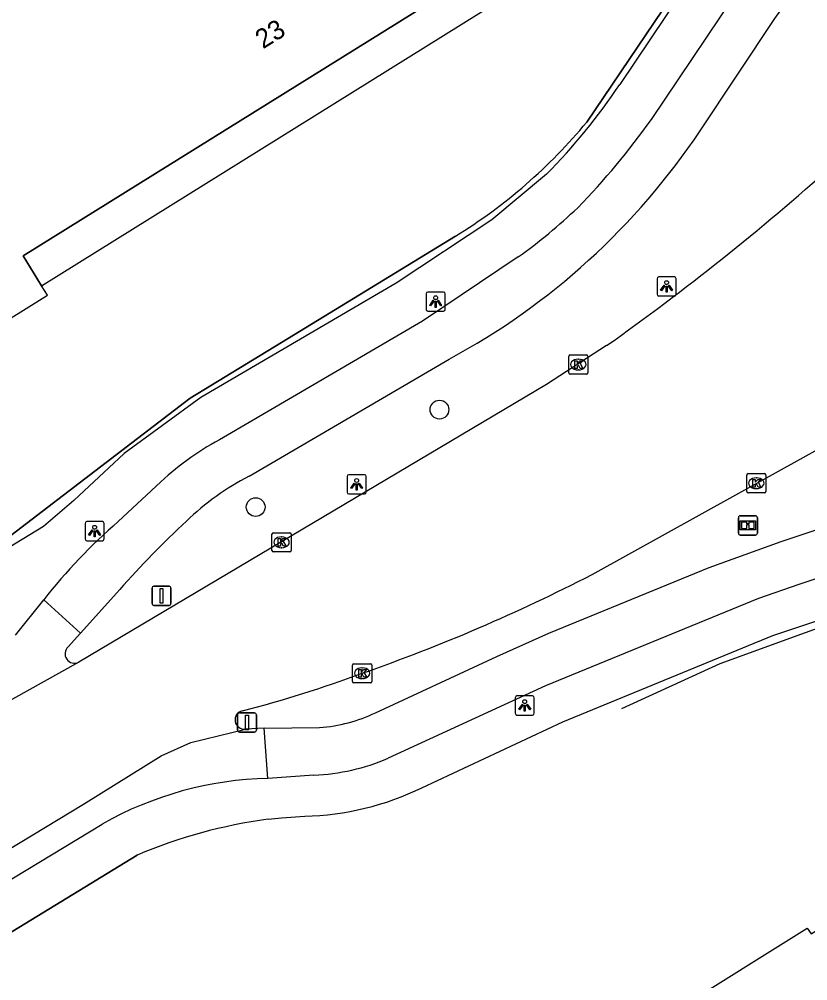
# Model space of a CAD drawing. Extents: x 156651 to 158072, y 387631 to 388990.
# Drawn here: x 157913 to 157954.1, y 388531.2 to 388581.4 of the extents above; entities that cross this region are included whole.
import ezdxf

# ---------------------------------------------------------------- set-up
doc = ezdxf.new("R2010")
doc.units = 0
for name, color, linetype in [('IMGEO_Boom', 7, 'Continuous'), ('IMGEO_Fietspad_open', 7, 'Continuous'), ('IMGEO_Groenvoorziening', 7, 'Continuous'), ('IMGEO_Hek', 7, 'Continuous'), ('IMGEO_Informatiebord', 7, 'Continuous'), ('IMGEO_Kolk', 7, 'Continuous'), ('IMGEO_Lichtpunt', 7, 'Continuous'), ('IMGEO_Muur', 7, 'Continuous'), ('IMGEO_Pand', 7, 'Continuous'), ('IMGEO_Pand_nummerreeks', 7, 'Continuous'), ('IMGEO_Pand_overbouw', 7, 'Continuous'), ('IMGEO_Rijbaan_lokaal_gesloten', 7, 'Continuous'), ('IMGEO_Verkeersbordpaal', 7, 'Continuous'), ('IMGEO_Voetpad_open', 7, 'Continuous')]:
    doc.layers.add(name, color=color, linetype=linetype)

msp = doc.modelspace()

# ---------------------------------------------------------------- linework, layer by layer
at = {"layer": 'IMGEO_Boom'}
for centre in [(157934.929, 388561.003), (157925.351, 388555.924)]:
    msp.add_circle(centre, 0.489, dxfattribs=at)
at = {"layer": 'IMGEO_Fietspad_open'}
for points in [[(157953.825, 388587.483), (157950.99, 388583.61), (157945.972, 388576.134)], [(157948.511, 388575.538), (157952.413, 388581.397), (157954.927, 388584.899)], [(157939.034, 388568.961), (157934.042, 388565.621), (157923.682, 388559.554)], [(157925.008, 388557.539), (157935.436, 388563.635)], [(157931.599, 388545.204), (157937.919, 388548.129), (157940.636, 388549.355), (157948.985, 388552.768), (157952.731, 388554.135), (157964.136, 388557.918), (157970.227, 388560.472)], [(157975.692, 388560.117), (157964.836, 388555.593), (157953.656, 388551.883), (157951.558, 388551.166), (157940.45, 388546.612), (157932.252, 388542.83)], [(157920.413, 388557.247), (157918.184, 388555.166)], [(157916.219, 388549.358), (157918.263, 388551.623)], [(157925.789, 388544.405), (157928.683, 388544.428)], [(157928.387, 388541.952), (157925.989, 388541.781)]]:
    msp.add_lwpolyline(points, dxfattribs=at)
for centre, radius, start, end in [((157915.537, 388597.592), 37.239, 315.5843, 324.8144), ((157918.015, 388595.904), 36.671, 298.3632, 326.264), ((157921.547, 388593.233), 29.915, 305.7707, 313.4907), ((157930.888, 388545.874), 15.461, 117.7771, 132.6457), ((157931.627, 388544.891), 14.275, 117.6236, 133.813), ((157937.074, 388533.312), 28.887, 130.8394, 142.0133), ((157957.425, 388516.909), 52.333, 132.985, 138.4453), ((157928.064, 388552.621), 8.216, 274.3205, 295.4837), ((157927.957, 388552.792), 10.848, 272.2725, 293.3245)]:
    msp.add_arc(centre, radius, start, end, dxfattribs=at)
at = {"layer": 'IMGEO_Groenvoorziening'}
for points in [[(157942.609, 388575.997), (157948.757, 388585.103), (157945.61, 388590.115), (157919.697, 388631.383), (157907.31, 388623.673)], [(157876.307, 388544.438), (157879.966, 388539.6), (157881.966, 388538.145), (157884.382, 388537.75), (157886.516, 388538.265), (157912.593, 388554.443), (157921.94, 388561.605), (157926.695, 388564.507), (157935.759, 388570.044)]]:
    msp.add_lwpolyline(points, dxfattribs=at)
msp.add_arc((157921.347, 388593.545), 27.568, 301.5184, 320.4662, dxfattribs=at)
at = {"layer": 'IMGEO_Hek'}
for points in [[(157945.61, 388590.115), (157948.757, 388585.103), (157942.609, 388575.997)], [(157935.759, 388570.044), (157926.695, 388564.507)], [(157926.695, 388564.507), (157921.94, 388561.605), (157912.593, 388554.443), (157886.516, 388538.265), (157884.382, 388537.75), (157881.966, 388538.145), (157879.966, 388539.6), (157876.307, 388544.438)], [(157919.17, 388537.784), (157901.376, 388526.898)]]:
    msp.add_lwpolyline(points, dxfattribs=at)
for centre, radius, start, end in [((157921.347, 388593.545), 27.568, 301.5184, 320.4662), ((157929.517, 388513.336), 26.547, 97.6193, 112.9393)]:
    msp.add_arc(centre, radius, start, end, dxfattribs=at)
at = {"layer": 'IMGEO_Informatiebord'}
for p, q in [((157950.508, 388554.568), (157950.508, 388555.368)), ((157950.508, 388555.368), (157950.508, 388554.568)), ((157950.608, 388555.468), (157951.398, 388555.468)), ((157951.398, 388555.468), (157950.608, 388555.468)), ((157951.498, 388555.368), (157951.498, 388554.568)), ((157951.498, 388554.568), (157951.498, 388555.368)), ((157951.398, 388554.468), (157950.608, 388554.468)), ((157950.608, 388554.468), (157951.398, 388554.468))]:
    msp.add_line(p, q, dxfattribs=at)
for points in [[(157950.609, 388555.2), (157951.397, 388555.2), (157951.397, 388554.736), (157950.609, 388554.736), (157950.609, 388555.2)], [(157950.674, 388555.135), (157950.674, 388554.801), (157950.949, 388554.801), (157950.95, 388555.014), (157951.054, 388555.015), (157951.055, 388554.801), (157951.332, 388554.801), (157951.332, 388555.135), (157951.056, 388555.135), (157951.056, 388555.055), (157950.95, 388555.055), (157950.95, 388555.135), (157950.674, 388555.135)]]:
    msp.add_lwpolyline(points, dxfattribs=at)
for centre, start, end in [((157950.608, 388555.368), 90, 180), ((157950.608, 388555.368), 90, 180), ((157951.398, 388555.368), 0, 90), ((157951.398, 388555.368), 360, 90), ((157950.608, 388554.568), 180, 270), ((157950.608, 388554.568), 180, 270), ((157951.398, 388554.568), 270, 0), ((157951.398, 388554.568), 270, 0)]:
    msp.add_arc(centre, 0.1, start, end, dxfattribs=at)
at = {"layer": 'IMGEO_Kolk'}
for p, q in [((157941.665, 388562.927), (157941.665, 388563.779)), ((157941.74, 388563.853), (157942.592, 388563.853)), ((157942.153, 388563.633), (157942.178, 388563.633)), ((157942.666, 388563.779), (157942.666, 388562.927)), ((157942.176, 388563.073), (157942.151, 388563.073)), ((157942.592, 388562.853), (157941.74, 388562.853)), ((157950.942, 388556.743), (157950.942, 388557.595)), ((157951.017, 388557.669), (157951.869, 388557.669)), ((157951.943, 388557.595), (157951.943, 388556.743)), ((157951.43, 388557.449), (157951.455, 388557.449)), ((157951.869, 388556.669), (157951.017, 388556.669)), ((157951.453, 388556.889), (157951.428, 388556.889)), ((157926.275, 388554.587), (157927.127, 388554.587)), ((157926.2, 388553.661), (157926.2, 388554.513)), ((157926.688, 388554.367), (157926.713, 388554.367)), ((157927.201, 388554.513), (157927.201, 388553.661)), ((157927.127, 388553.587), (157926.275, 388553.587)), ((157926.711, 388553.807), (157926.686, 388553.807)), ((157930.4, 388546.834), (157930.4, 388547.686)), ((157930.475, 388547.76), (157931.327, 388547.76)), ((157930.888, 388547.54), (157930.913, 388547.54)), ((157931.401, 388547.686), (157931.401, 388546.834)), ((157931.327, 388546.76), (157930.475, 388546.76)), ((157930.911, 388546.98), (157930.886, 388546.98))]:
    msp.add_line(p, q, dxfattribs=at)
for points in [[(157941.665, 388562.927), (157941.665, 388563.779)], [(157941.74, 388563.853), (157942.592, 388563.853)], [(157941.986, 388563.553), (157942.109, 388563.553), (157942.109, 388563.402), (157942.239, 388563.553), (157942.403, 388563.553), (157942.257, 388563.402), (157942.41, 388563.153), (157942.258, 388563.153), (157942.173, 388563.317), (157942.109, 388563.25), (157942.109, 388563.153), (157941.986, 388563.153), (157941.986, 388563.553)], [(157942.666, 388563.779), (157942.666, 388562.927)], [(157942.592, 388562.853), (157941.74, 388562.853)], [(157950.942, 388556.743), (157950.942, 388557.595)], [(157951.017, 388557.669), (157951.869, 388557.669)], [(157951.943, 388557.595), (157951.943, 388556.743)], [(157951.263, 388557.369), (157951.386, 388557.369), (157951.386, 388557.218), (157951.516, 388557.369), (157951.68, 388557.369), (157951.534, 388557.218), (157951.687, 388556.969), (157951.535, 388556.969), (157951.45, 388557.133), (157951.386, 388557.066), (157951.386, 388556.969), (157951.263, 388556.969), (157951.263, 388557.369)], [(157951.869, 388556.669), (157951.017, 388556.669)], [(157926.275, 388554.587), (157927.127, 388554.587)], [(157926.2, 388553.661), (157926.2, 388554.513)], [(157926.521, 388554.287), (157926.644, 388554.287), (157926.644, 388554.136), (157926.774, 388554.287), (157926.938, 388554.287), (157926.792, 388554.136), (157926.945, 388553.887), (157926.793, 388553.887), (157926.708, 388554.051), (157926.644, 388553.984), (157926.644, 388553.887), (157926.521, 388553.887), (157926.521, 388554.287)], [(157927.201, 388554.513), (157927.201, 388553.661)], [(157927.127, 388553.587), (157926.275, 388553.587)], [(157930.4, 388546.834), (157930.4, 388547.686)], [(157930.475, 388547.76), (157931.327, 388547.76)], [(157931.401, 388547.686), (157931.401, 388546.834)], [(157930.721, 388547.46), (157930.844, 388547.46), (157930.844, 388547.309), (157930.974, 388547.46), (157931.138, 388547.46), (157930.992, 388547.309), (157931.145, 388547.06), (157930.993, 388547.06), (157930.908, 388547.224), (157930.844, 388547.157), (157930.844, 388547.06), (157930.721, 388547.06), (157930.721, 388547.46)], [(157931.327, 388546.76), (157930.475, 388546.76)]]:
    msp.add_lwpolyline(points, dxfattribs=at)
for centre, start, end in [((157941.742, 388563.777), 91.552, 178.448), ((157941.742, 388563.777), 91.552, 178.448), ((157942.59, 388563.777), 1.552, 88.448), ((157942.59, 388563.777), 1.552, 88.448), ((157941.742, 388562.929), 181.552, 268.448), ((157941.742, 388562.929), 181.552, 268.448), ((157942.59, 388562.929), 271.552, 358.448), ((157942.59, 388562.929), 271.552, 358.448), ((157951.019, 388557.593), 91.552, 178.448), ((157951.019, 388557.593), 91.552, 178.448), ((157951.867, 388557.593), 1.552, 88.448), ((157951.867, 388557.593), 1.552, 88.448), ((157951.019, 388556.745), 181.552, 268.448), ((157951.019, 388556.745), 181.552, 268.448), ((157951.867, 388556.745), 271.552, 358.448), ((157951.867, 388556.745), 271.552, 358.448), ((157926.277, 388554.511), 91.552, 178.448), ((157926.277, 388554.511), 91.552, 178.448), ((157927.125, 388554.511), 1.552, 88.448), ((157927.125, 388554.511), 1.552, 88.448), ((157926.277, 388553.663), 181.552, 268.448), ((157926.277, 388553.663), 181.552, 268.448), ((157927.125, 388553.663), 271.552, 358.448), ((157927.125, 388553.663), 271.552, 358.448), ((157930.477, 388547.684), 91.552, 178.448), ((157930.477, 388547.684), 91.552, 178.448), ((157931.325, 388547.684), 1.552, 88.448), ((157931.325, 388547.684), 1.552, 88.448), ((157930.477, 388546.836), 181.552, 268.448), ((157930.477, 388546.836), 181.552, 268.448), ((157931.325, 388546.836), 271.552, 358.448), ((157931.325, 388546.836), 271.552, 358.448)]:
    msp.add_arc(centre, 0.0765, start, end, dxfattribs=at)
for centre, major_axis, ratio, start_param, end_param in [((157942.152, 388563.353), (-0.387, 0.002), 0.722429, 4.712389, 7.853982), ((157942.177, 388563.353), (-0.39, 0.002), 0.717154, 1.570796, 4.712389), ((157951.429, 388557.169), (-0.387, 0.002), 0.722429, 4.712389, 7.853982), ((157951.454, 388557.169), (-0.39, 0.002), 0.717154, 1.570796, 4.712389), ((157926.687, 388554.087), (-0.387, 0.002), 0.722429, 4.712389, 7.853982), ((157926.712, 388554.087), (-0.39, 0.002), 0.717154, 1.570796, 4.712389), ((157930.887, 388547.26), (-0.387, 0.002), 0.722429, 4.712389, 7.853982), ((157930.912, 388547.26), (-0.39, 0.002), 0.717154, 1.570796, 4.712389)]:
    msp.add_ellipse(centre, major_axis=major_axis, ratio=ratio, start_param=start_param, end_param=end_param, dxfattribs=at)
at = {"layer": 'IMGEO_Lichtpunt'}
for p, q in [((157946.27, 388567.828), (157946.27, 388567.021)), ((157946.27, 388567.828), (157946.27, 388567.021)), ((157947.172, 388567.923), (157946.364, 388567.923)), ((157947.172, 388567.923), (157946.364, 388567.923)), ((157947.266, 388567.021), (157947.266, 388567.828)), ((157947.266, 388567.021), (157947.266, 388567.828)), ((157935.135, 388567.133), (157934.327, 388567.133)), ((157935.135, 388567.133), (157934.327, 388567.133)), ((157934.233, 388567.038), (157934.233, 388566.231)), ((157934.233, 388567.038), (157934.233, 388566.231)), ((157935.229, 388566.231), (157935.229, 388567.038)), ((157935.229, 388566.231), (157935.229, 388567.038)), ((157946.364, 388566.927), (157947.172, 388566.927)), ((157946.364, 388566.927), (157947.172, 388566.927)), ((157934.327, 388566.137), (157935.135, 388566.137)), ((157934.327, 388566.137), (157935.135, 388566.137)), ((157931.017, 388557.608), (157930.209, 388557.608)), ((157931.017, 388557.608), (157930.209, 388557.608)), ((157930.115, 388557.513), (157930.115, 388556.706)), ((157930.115, 388557.513), (157930.115, 388556.706)), ((157931.111, 388556.706), (157931.111, 388557.513)), ((157931.111, 388556.706), (157931.111, 388557.513)), ((157930.209, 388556.612), (157931.017, 388556.612)), ((157930.209, 388556.612), (157931.017, 388556.612)), ((157916.458, 388555.073), (157916.458, 388554.266)), ((157916.458, 388555.073), (157916.458, 388554.266)), ((157917.36, 388555.168), (157916.552, 388555.168)), ((157917.36, 388555.168), (157916.552, 388555.168)), ((157917.454, 388554.266), (157917.454, 388555.073)), ((157917.454, 388554.266), (157917.454, 388555.073)), ((157916.552, 388554.172), (157917.36, 388554.172)), ((157916.552, 388554.172), (157917.36, 388554.172)), ((157939.777, 388546.081), (157938.969, 388546.081)), ((157939.777, 388546.081), (157938.969, 388546.081)), ((157938.875, 388545.986), (157938.875, 388545.179)), ((157938.875, 388545.986), (157938.875, 388545.179)), ((157939.871, 388545.179), (157939.871, 388545.986)), ((157939.871, 388545.179), (157939.871, 388545.986)), ((157938.969, 388545.085), (157939.777, 388545.085)), ((157938.969, 388545.085), (157939.777, 388545.085))]:
    msp.add_line(p, q, dxfattribs=at)
for points in [[(157946.644, 388567.492), (157946.683, 388567.464), (157946.495, 388567.202), (157946.457, 388567.229), (157946.644, 388567.492)], [(157946.746, 388567.444), (157946.793, 388567.444), (157946.793, 388567.122), (157946.746, 388567.122), (157946.746, 388567.444)], [(157946.856, 388567.464), (157946.894, 388567.491), (157947.081, 388567.229), (157947.042, 388567.201), (157946.856, 388567.464)], [(157934.607, 388566.702), (157934.646, 388566.674), (157934.458, 388566.412), (157934.42, 388566.439), (157934.607, 388566.702)], [(157934.709, 388566.654), (157934.756, 388566.654), (157934.756, 388566.332), (157934.709, 388566.332), (157934.709, 388566.654)], [(157934.819, 388566.674), (157934.857, 388566.701), (157935.044, 388566.439), (157935.005, 388566.411), (157934.819, 388566.674)], [(157930.489, 388557.177), (157930.528, 388557.149), (157930.34, 388556.887), (157930.302, 388556.914), (157930.489, 388557.177)], [(157930.591, 388557.129), (157930.638, 388557.129), (157930.638, 388556.807), (157930.591, 388556.807), (157930.591, 388557.129)], [(157930.701, 388557.149), (157930.739, 388557.176), (157930.926, 388556.914), (157930.887, 388556.886), (157930.701, 388557.149)], [(157916.832, 388554.737), (157916.871, 388554.709), (157916.683, 388554.447), (157916.645, 388554.474), (157916.832, 388554.737)], [(157916.934, 388554.689), (157916.981, 388554.689), (157916.981, 388554.367), (157916.934, 388554.367), (157916.934, 388554.689)], [(157917.044, 388554.709), (157917.082, 388554.736), (157917.269, 388554.474), (157917.23, 388554.446), (157917.044, 388554.709)], [(157939.249, 388545.65), (157939.288, 388545.622), (157939.1, 388545.36), (157939.062, 388545.387), (157939.249, 388545.65)], [(157939.351, 388545.602), (157939.398, 388545.602), (157939.398, 388545.28), (157939.351, 388545.28), (157939.351, 388545.602)], [(157939.461, 388545.622), (157939.499, 388545.649), (157939.686, 388545.387), (157939.647, 388545.359), (157939.461, 388545.622)]]:
    msp.add_lwpolyline(points, dxfattribs=at)
for centre in [(157946.769, 388567.626), (157934.732, 388566.836), (157930.614, 388557.311), (157916.957, 388554.871), (157939.374, 388545.784)]:
    msp.add_circle(centre, 0.0994, dxfattribs=at)
for centre, start, end in [((157946.364, 388567.828), 90, 180), ((157946.364, 388567.828), 90, 180), ((157947.172, 388567.828), 0, 90), ((157947.172, 388567.828), 0, 90), ((157934.327, 388567.038), 90, 180), ((157934.327, 388567.038), 90, 180), ((157935.135, 388567.038), 0, 90), ((157935.135, 388567.038), 0, 90), ((157946.364, 388567.021), 180, 270), ((157946.364, 388567.021), 180, 270), ((157947.172, 388567.021), 270, 0), ((157947.172, 388567.021), 270, 360), ((157934.327, 388566.231), 180, 270), ((157934.327, 388566.231), 180, 270), ((157935.135, 388566.231), 270, 0), ((157935.135, 388566.231), 270, 360), ((157930.209, 388557.513), 90, 180), ((157930.209, 388557.513), 90, 180), ((157931.017, 388557.513), 0, 90), ((157931.017, 388557.513), 0, 90), ((157930.209, 388556.706), 180, 270), ((157930.209, 388556.706), 180, 270), ((157931.017, 388556.706), 270, 0), ((157931.017, 388556.706), 270, 360), ((157916.552, 388555.073), 90, 180), ((157916.552, 388555.073), 90, 180), ((157917.36, 388555.073), 0, 90), ((157917.36, 388555.073), 0, 90), ((157916.552, 388554.266), 180, 270), ((157916.552, 388554.266), 180, 270), ((157917.36, 388554.266), 270, 0), ((157917.36, 388554.266), 270, 360), ((157938.969, 388545.986), 90, 180), ((157938.969, 388545.986), 90, 180), ((157939.777, 388545.986), 0, 90), ((157939.777, 388545.986), 0, 90), ((157938.969, 388545.179), 180, 270), ((157938.969, 388545.179), 180, 270), ((157939.777, 388545.179), 270, 0), ((157939.777, 388545.179), 270, 360)]:
    msp.add_arc(centre, 0.0946, start, end, dxfattribs=at)
at = {"layer": 'IMGEO_Muur'}
msp.add_lwpolyline([(157944.436, 388545.424), (157949.561, 388547.765), (157976.054, 388557.403), (157979.433, 388551.896)], dxfattribs=at)
at = {"layer": 'IMGEO_Pand'}
for points in [[(157914.19, 388567.452), (157913.225, 388569.027), (157942.615, 388587.321), (157933.319, 388602.195), (157924.551, 388596.738), (157917.093, 388592.095), (157902.499, 388615.468), (157898.345, 388612.873), (157889.39, 388607.278), (157889.176, 388607.593), (157883.007, 388603.739), (157883.193, 388603.423), (157865.87, 388592.617), (157891.158, 388552.943), (157908.075, 388563.555), (157908.34, 388563.13), (157914.494, 388566.97), (157914.19, 388567.452)], [(157954.097, 388533.97), (157954.301, 388533.683), (157958.588, 388536.358), (157966.066, 388541.038), (157973.749, 388528.738), (157974.94, 388529.477), (157993.887, 388499.128), (157980.909, 388491.057), (157981.094, 388490.76), (157946.508, 388469.137), (157919.498, 388512.339), (157954.097, 388533.97)]]:
    msp.add_lwpolyline(points, dxfattribs=at)
at = {"layer": 'IMGEO_Pand_overbouw'}
msp.add_lwpolyline([(157943.658, 388585.673), (157943.147, 388586.459), (157942.615, 388587.321), (157913.225, 388569.027), (157914.19, 388567.452), (157942.786, 388585.292), (157942.858, 388585.18)], close=True, dxfattribs=at)
at = {"layer": 'IMGEO_Rijbaan_lokaal_gesloten'}
for points in [[(157942.886, 388552.412), (157967.098, 388565.84)], [(157943.644, 388564.341), (157940.508, 388562.306), (157916.133, 388547.836)], [(157912.832, 388549.247), (157914.307, 388551.091)], [(157914.307, 388551.091), (157916.219, 388549.358)], [(157916.219, 388549.358), (157915.575, 388548.644)], [(157916.133, 388547.836), (157910.853, 388544.897), (157894.34, 388534.897)], [(157801.977, 388465.115), (157808.05, 388470.514), (157814.126, 388475.59), (157822.012, 388481.702), (157827.136, 388485.429), (157832.229, 388488.942), (157838.65, 388493.098), (157881.592, 388519.374), (157884.271, 388521.013), (157916.373, 388540.433), (157920.425, 388542.954), (157921.978, 388543.651), (157924.816, 388544.354)], [(157925.789, 388544.405), (157924.816, 388544.354)], [(157925.989, 388541.781), (157925.789, 388544.405)], [(157900.08, 388528.956), (157917.35, 388539.403)]]:
    msp.add_lwpolyline(points, dxfattribs=at)
for centre, radius, start, end in [((157866.867, 388672.709), 132.809, 305.31667, 311.81023), ((157900.199, 388635.198), 93.143, 289.2458, 297.27711), ((157915.911, 388548.279), 0.496, 132.6143, 296.6432), ((157908.86, 388606.7), 63.395, 284.4304, 290.34557), ((157924.758, 388544.833), 0.482, 101.9591, 276.9069), ((157926.423, 388523.323), 18.463, 91.3472, 119.4333)]:
    msp.add_arc(centre, radius, start, end, dxfattribs=at)
at = {"layer": 'IMGEO_Verkeersbordpaal'}
for p, q in [((157919.948, 388550.898), (157919.948, 388551.698)), ((157919.948, 388551.698), (157919.948, 388550.898)), ((157920.048, 388551.798), (157920.838, 388551.798)), ((157920.838, 388551.798), (157920.048, 388551.798)), ((157920.938, 388551.698), (157920.938, 388550.898)), ((157920.938, 388550.898), (157920.938, 388551.698)), ((157920.838, 388550.798), (157920.048, 388550.798)), ((157920.048, 388550.798), (157920.838, 388550.798)), ((157924.402, 388544.295), (157924.402, 388545.095)), ((157924.402, 388545.095), (157924.402, 388544.295)), ((157924.502, 388545.195), (157925.292, 388545.195)), ((157925.292, 388545.195), (157924.502, 388545.195)), ((157925.392, 388545.095), (157925.392, 388544.295)), ((157925.392, 388544.295), (157925.392, 388545.095)), ((157925.292, 388544.195), (157924.502, 388544.195)), ((157924.502, 388544.195), (157925.292, 388544.195))]:
    msp.add_line(p, q, dxfattribs=at)
for points in [[(157920.368, 388551.673), (157920.518, 388551.673), (157920.518, 388550.923), (157920.368, 388550.923), (157920.368, 388551.673)], [(157924.822, 388545.07), (157924.972, 388545.07), (157924.972, 388544.32), (157924.822, 388544.32), (157924.822, 388545.07)]]:
    msp.add_lwpolyline(points, dxfattribs=at)
for centre, start, end in [((157920.048, 388551.698), 90, 180), ((157920.048, 388551.698), 90, 180), ((157920.838, 388551.698), 0, 90), ((157920.838, 388551.698), 360, 90), ((157920.048, 388550.898), 180, 270), ((157920.048, 388550.898), 180, 270), ((157920.838, 388550.898), 270, 0), ((157920.838, 388550.898), 270, 0), ((157924.502, 388545.095), 90, 180), ((157924.502, 388545.095), 90, 180), ((157925.292, 388545.095), 0, 90), ((157925.292, 388545.095), 360, 90), ((157924.502, 388544.295), 180, 270), ((157924.502, 388544.295), 180, 270), ((157925.292, 388544.295), 270, 0), ((157925.292, 388544.295), 270, 0)]:
    msp.add_arc(centre, 0.1, start, end, dxfattribs=at)
at = {"layer": 'IMGEO_Voetpad_open'}
for points in [[(157949.123, 388585.105), (157944.325, 388577.946)], [(157940.514, 388573.276), (157937.655, 388570.903), (157932.675, 388567.591), (157922.488, 388561.637), (157918.49, 388558.725), (157915.878, 388556.27), (157914.286, 388554.915), (157886.442, 388537.927)], [(157934.019, 388541.297), (157941.368, 388544.728), (157952.302, 388549.233), (157965.677, 388553.684), (157977.603, 388558.657)], [(157925.997, 388539.649), (157926.691, 388539.731), (157927.906, 388539.814)], [(157901.376, 388526.898), (157919.17, 388537.784)]]:
    msp.add_lwpolyline(points, dxfattribs=at)
for centre, radius, start, end in [((157917.286, 388596.121), 32.579, 315.4756, 326.0914), ((157927.594, 388554.439), 14.629, 271.2208, 296.052), ((157929.517, 388513.336), 26.547, 97.6193, 112.9393)]:
    msp.add_arc(centre, radius, start, end, dxfattribs=at)

# ---------------------------------------------------------------- texts
at = {"layer": 'IMGEO_Pand_nummerreeks'}
msp.add_text('23', height=1, rotation=31.9001, dxfattribs=at).set_placement((157925.732, 388579.78))

doc.saveas('drawing.dxf')
